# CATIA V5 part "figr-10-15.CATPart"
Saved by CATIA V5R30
Part number: Part1
Bounding box of the stored display mesh (mm): x -59.023 to 59.085, y -59.069 to 29.542, z 0 to 150
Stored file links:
  D:\PROJECTS\CATIA V56R 2020\Resources\Parts File\c10_catia_v5_6r2020_prt\figr-10-15.CATPart
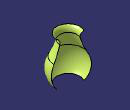
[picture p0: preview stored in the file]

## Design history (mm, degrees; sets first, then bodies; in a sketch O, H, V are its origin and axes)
Set1
  Sketch1 on yz-plane, origin (0, 0, 0), H (0, 1, 0), V (0, 0, 1)
    arc A1 centre (219.5293, 176.8574) radius 194.8379 from (50.3627, 80.1907) to (30.3627, 130.1907) cw
    arc A2 centre (-7.8186, 46.9443) radius 67.0103 from (50.3627, 80.1907) to (40, 0) cw
    arc A3 centre (47.0688, 134.312) radius 17.207 from (30.3627, 130.1907) to (40, 150) cw
    axis line L1 (0, 156.5671) -> (0, -24.1442)
    vertical: L1 V
  Revol1: Element1 Sketch1, Angle1 -60
Body1 (main body)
